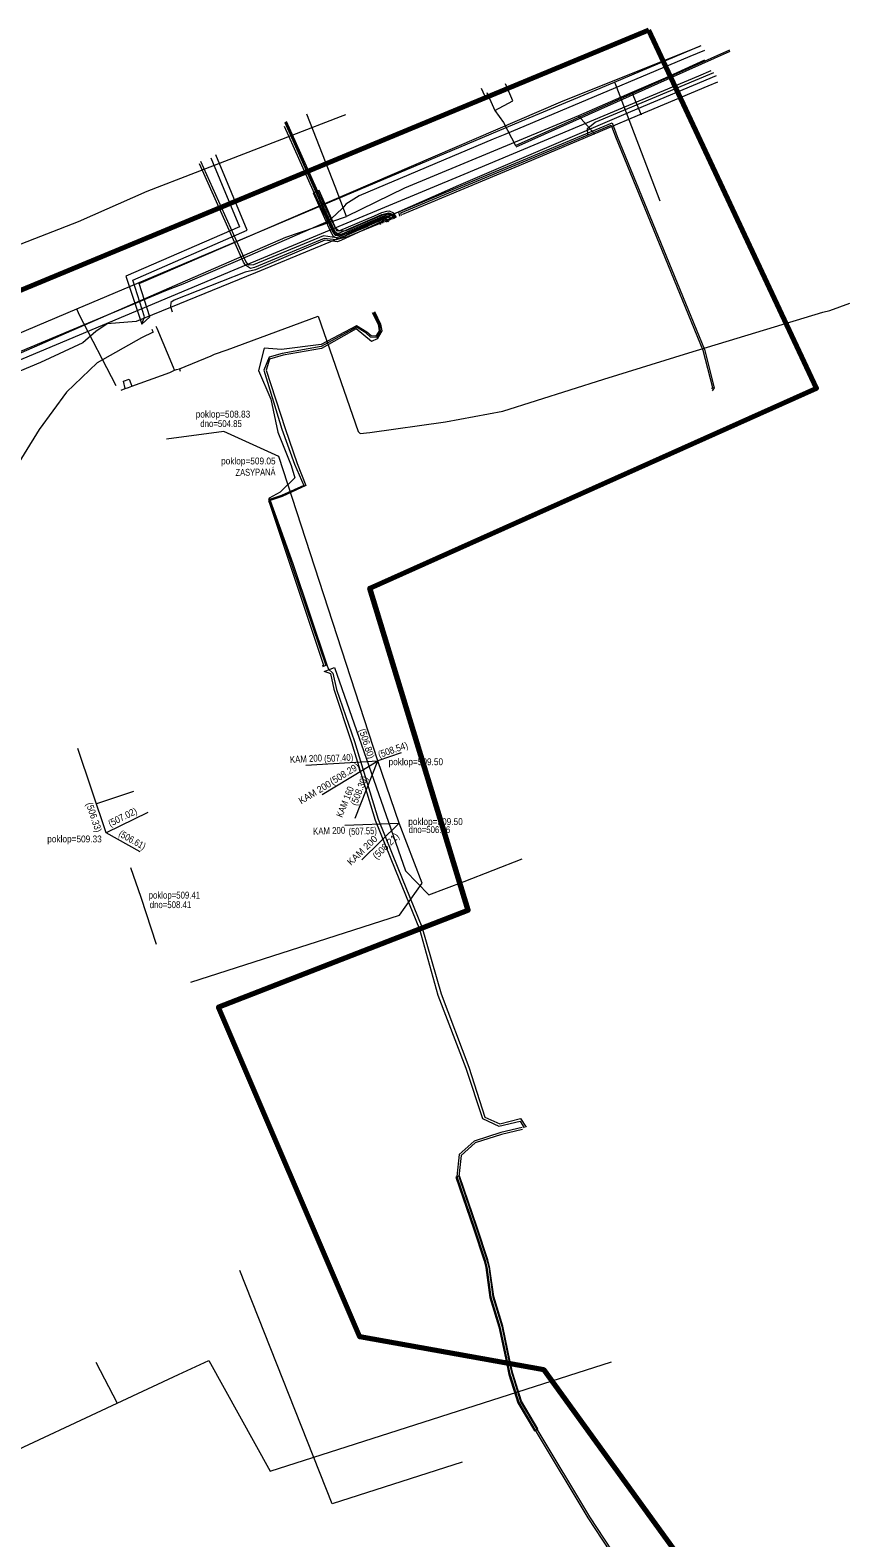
# Model space of a CAD drawing. Extents: x -669700 to -669482, y -1129632 to -1129394.
# Drawn here: x -669565.5 to -669482, y -1129547.5 to -1129393.9 of the extents above; entities that cross this region are included whole.
import ezdxf
from ezdxf.enums import TextEntityAlignment as Align

# ---------------------------------------------------------------- set-up
doc = ezdxf.new("R2010")
doc.units = 0
doc.header["$LTSCALE"] = 0.28
for name, color, linetype, lineweight in [('1', 7, 'Continuous', 13), ('12', 7, 'Continuous', 13), ('13', 7, 'Continuous', 13), ('21', 7, 'Continuous', 13), ('24', 7, 'Continuous', 13), ('27', 7, 'Continuous', 13), ('3', 7, 'Continuous', 13), ('33', 7, 'Continuous', 13), ('43', 7, 'Continuous', 13), ('53', 7, 'Continuous', 13), ('54', 7, 'Continuous', 13), ('57', 7, 'Continuous', 70), ('7', 7, 'Continuous', 13)]:
    doc.layers.add(name, color=color, linetype=linetype, lineweight=lineweight)
doc.layers.add('59', color=7, linetype='Continuous')

msp = doc.modelspace()

# ---------------------------------------------------------------- linework, layer by layer
at = {"layer": '1'}
msp.add_lwpolyline([(-669496.851, -1129395.943), (-669498.33, -1129396.56), (-669511.52, -1129402.13), (-669517.18, -1129404.52), (-669518.35, -1129405), (-669532, -1129410.77), (-669533.35, -1129411.61), (-669533.55, -1129411.87), (-669533.74, -1129412.06), (-669534.83, -1129413.08), (-669535.13, -1129413.35), (-669543.92, -1129417.17), (-669549.97, -1129419.77), (-669551.71, -1129420.43), (-669552.78, -1129420.88), (-669561.46, -1129424.52), (-669573.43, -1129429.51)], dxfattribs=at)
at = {"layer": '12'}
for p, q in [((-669516.08, -1129405.62), (-669494.27, -1129395.9)), ((-669516.36, -1129401.09), (-669517.11, -1129399.37)), ((-669518.2, -1129402.06), (-669516.36, -1129401.09)), ((-669517.31, -1129403.28), (-669516.08, -1129405.62))]:
    msp.add_line(p, q, dxfattribs=at)
for points in [[(-669496.193, -1129398.031), (-669497.44, -1129398.56), (-669521.35, -1129408.58), (-669544.75, -1129418.35), (-669569.27, -1129428.64), (-669593.24, -1129438.67), (-669594.77, -1129439.37), (-669598.74, -1129442.19), (-669598.99, -1129442.41), (-669613.69, -1129455.56), (-669636.45, -1129475.92), (-669654.71, -1129492.21), (-669673.86, -1129509.44), (-669690.21, -1129524.03), (-669693.504, -1129526.678)], [(-669519.01, -1129400.25), (-669518.2, -1129402.06), (-669517.31, -1129403.28)]]:
    msp.add_lwpolyline(points, dxfattribs=at)
at = {"layer": '13'}
for p, q in [((-669516.019, -1129405.757), (-669494.209, -1129396.037)), ((-669558.81, -1129529.58), (-669556.63, -1129533.77)), ((-669580.87, -1129545.11), (-669556.63, -1129533.77))]:
    msp.add_line(p, q, dxfattribs=at)
for points in [[(-669508.71, -1129404.56), (-669508.75, -1129403.9), (-669507.98, -1129403.27), (-669495.868, -1129398.207)], [(-669535.58, -1129459.21), (-669534.5, -1129458.83), (-669527.28, -1129479.55), (-669524.92, -1129481.99), (-669521.32, -1129480.61), (-669515.406, -1129478.323)], [(-669556.63, -1129533.77), (-669550.41, -1129530.86), (-669547.32, -1129529.43), (-669541.05, -1129540.7), (-669506.304, -1129529.571)]]:
    msp.add_lwpolyline(points, dxfattribs=at)
at = {"layer": '21'}
for p, q in [((-669504.25, -1129400.25), (-669503.28, -1129402.52)), ((-669509.66, -1129402.6), (-669508.01, -1129404.49)), ((-669550.3, -1129428.39), (-669550.22, -1129428.62))]:
    msp.add_line(p, q, dxfattribs=at)
for points in [[(-669496.845, -1129396.94), (-669500.84, -1129398.77), (-669504.25, -1129400.25), (-669509.66, -1129402.6), (-669527.39, -1129409.97), (-669533.28, -1129412.87)], [(-669533.28, -1129412.87), (-669534.46, -1129409.81), (-669537.33, -1129402.455)], [(-669550.23, -1129419.66), (-669539.46, -1129414.96), (-669533.28, -1129412.87)], [(-669553.131, -1129424.348), (-669553.08, -1129424.45), (-669552.97, -1129424.66), (-669554.16, -1129425.23), (-669558.7, -1129427.79), (-669561.79, -1129430.76), (-669564.58, -1129434.58), (-669567.92, -1129439.98), (-669576.65, -1129451.91), (-669580.3, -1129456.57), (-669581.62, -1129458.81), (-669581.92, -1129461.49), (-669580.27, -1129467.8), (-669579.78, -1129469.59), (-669577.05, -1129477.92), (-669576.91, -1129478.41), (-669576.3, -1129480.12), (-669576.78, -1129480.36), (-669579.92, -1129481.77), (-669581.02, -1129482.2), (-669583.11, -1129482.87), (-669583.18, -1129482.9)], [(-669550.81, -1129428.51), (-669550.92, -1129428.26), (-669552.59, -1129424.27), (-669552.67, -1129424.09)]]:
    msp.add_lwpolyline(points, dxfattribs=at)
at = {"layer": '24'}
for points in [[(-669664.58, -1129499.83), (-669597.43, -1129440.26), (-669550.23, -1129419.66)], [(-669550.81, -1129428.51), (-669550.59, -1129428.47), (-669550.3, -1129428.39), (-669547.09, -1129427.05), (-669546.74, -1129426.89), (-669545.43, -1129426.45), (-669536.18, -1129423.03), (-669532.09, -1129434.77), (-669531.9, -1129434.99), (-669530.92, -1129434.86), (-669523.2, -1129433.78), (-669517.38, -1129432.71), (-669507.08, -1129429.43), (-669498.43, -1129426.77), (-669484.77, -1129422.63), (-669484.08, -1129422.44), (-669482.034, -1129421.713)], [(-669521.528, -1129539.77), (-669534.742, -1129544.022), (-669544.16, -1129520.24)]]:
    msp.add_lwpolyline(points, dxfattribs=at)
at = {"layer": '27'}
msp.add_line((-669555.82, -1129430.39), (-669555.485, -1129430.28), dxfattribs=at)
for points in [[(-669556.25, -1129430.57), (-669555.82, -1129430.39), (-669556.01, -1129429.65), (-669555.42, -1129429.46), (-669555.27, -1129429.87), (-669555.15, -1129430.17)], [(-669555.485, -1129430.28), (-669555.15, -1129430.17), (-669551.29, -1129428.75), (-669550.81, -1129428.51)]]:
    msp.add_lwpolyline(points, dxfattribs=at)
at = {"layer": '3'}
for points in [[(-669554.15, -1129423.85), (-669553.32, -1129423.1), (-669554.41, -1129419.7), (-669511.48, -1129401.19), (-669497.307, -1129395.524)], [(-669529.586, -1129413.549), (-669529.64, -1129413.271), (-669529.39, -1129413.007), (-669521.845, -1129409.674), (-669504.35, -1129402.165), (-669495.603, -1129398.504)], [(-669527.538, -1129412.689), (-669527.544, -1129412.623), (-669526.927, -1129412.353), (-669515.718, -1129407.674), (-669505.887, -1129403.539), (-669504.292, -1129402.837), (-669496.461, -1129399.542), (-669495.491, -1129399.134)], [(-669529.103, -1129413.449), (-669529.399, -1129413.086), (-669529.63, -1129413.14), (-669533.26, -1129414.64), (-669534.09, -1129414.82), (-669534.44, -1129414.64), (-669534.7, -1129414.21), (-669535.44, -1129412.56), (-669536.41, -1129410.35), (-669539.526, -1129403.331)], [(-669528.988, -1129413.402), (-669529.341, -1129412.973), (-669529.59, -1129413.02), (-669533.28, -1129414.62), (-669534.11, -1129414.69), (-669534.35, -1129414.55), (-669534.65, -1129414.26), (-669535.42, -1129412.4), (-669536.37, -1129410.34), (-669539.515, -1129403.257)], [(-669528.194, -1129412.98), (-669528.473, -1129412.526), (-669528.918, -1129412.334), (-669529.205, -1129412.351), (-669529.743, -1129412.507), (-669530.46, -1129412.826), (-669534.017, -1129414.34), (-669534.209, -1129414.363), (-669534.342, -1129414.191), (-669535.031, -1129412.805), (-669536.334, -1129410.007), (-669539.414, -1129403.181)], [(-669527.866, -1129412.835), (-669527.965, -1129412.394), (-669506.238, -1129403.315), (-669505.725, -1129404.706), (-669496.842, -1129426.424), (-669495.833, -1129430.34), (-669496.051, -1129430.625)], [(-669527.701, -1129412.762), (-669527.76, -1129412.5), (-669506.34, -1129403.55), (-669505.89, -1129404.77), (-669497.01, -1129426.48), (-669496.026, -1129430.301), (-669496.129, -1129430.436)], [(-669547.106, -1129406.904), (-669544.19, -1129413.93), (-669555.75, -1129418.96), (-669554.15, -1129423.85), (-669553.85, -1129423.1), (-669555.06, -1129419.34), (-669543.41, -1129414.27), (-669546.592, -1129406.589)], [(-669528.736, -1129413.221), (-669528.872, -1129413.122), (-669529.048, -1129412.986), (-669529.532, -1129413.138), (-669533.903, -1129415.092), (-669534.33, -1129415.239), (-669535.552, -1129415.099), (-669542.67, -1129418.083), (-669543.072, -1129418.165), (-669543.589, -1129417.844), (-669543.79, -1129417.526), (-669548.265, -1129407.52)], [(-669528.595, -1129413.158), (-669528.778, -1129412.956), (-669529.046, -1129412.824), (-669529.593, -1129412.981), (-669533.986, -1129414.914), (-669534.327, -1129415.027), (-669535.648, -1129414.854), (-669542.764, -1129417.788), (-669543.244, -1129417.832), (-669543.552, -1129417.443), (-669548.12, -1129407.256)], [(-669529.803, -1129413.675), (-669530.029, -1129413.31), (-669530.213, -1129413.348), (-669530.864, -1129413.674), (-669531.217, -1129413.925), (-669536.492, -1129416.091), (-669542.545, -1129418.613), (-669554.722, -1129423.573), (-669557.657, -1129423.8), (-669558.831, -1129424.585), (-669560.14, -1129425.741), (-669564.467, -1129427.729), (-669594.248, -1129440.232), (-669598.12, -1129442.702), (-669644.235, -1129483.951), (-669685.258, -1129519.89), (-669686.935, -1129521.259), (-669687.43, -1129521.755), (-669687.51, -1129522.187), (-669687.241, -1129522.483), (-669687.013, -1129522.747)], [(-669528.893, -1129413.29), (-669529.087, -1129413.18), (-669529.447, -1129413.292), (-669533.815, -1129415.277), (-669534.214, -1129415.446), (-669535.483, -1129415.288), (-669542.561, -1129418.292), (-669543.613, -1129418.539), (-669550.839, -1129421.402), (-669551.19, -1129421.638), (-669551.205, -1129422.037), (-669551.04, -1129422.594)], [(-669530.672, -1129422.667), (-669530.073, -1129423.853), (-669529.963, -1129424.515), (-669530.291, -1129425.073), (-669530.772, -1129425.022), (-669531.222, -1129424.663), (-669532.262, -1129424.008), (-669535.88, -1129425.92), (-669539.9, -1129426.42), (-669541.66, -1129426.27), (-669542.26, -1129428.55), (-669541.01, -1129431.48), (-669540.29, -1129434.83), (-669538.94, -1129438.25), (-669538.55, -1129439.51), (-669540.06, -1129440.97), (-669541.16, -1129441.56), (-669541.22, -1129441.79), (-669541.072, -1129442.279), (-669535.621, -1129458.579), (-669535.756, -1129458.635)], [(-669530.554, -1129422.617), (-669529.94, -1129423.9), (-669529.85, -1129424.56), (-669530.24, -1129425.2), (-669530.85, -1129425.18), (-669531.33, -1129424.72), (-669532.28, -1129424.16), (-669535.88, -1129426.13), (-669539.83, -1129426.82), (-669541.16, -1129427.21), (-669541.7, -1129428.52), (-669539.88, -1129434.55), (-669538.6, -1129438.12), (-669537.65, -1129440.26), (-669539.91, -1129441.31), (-669541.15, -1129441.7), (-669541.1, -1129441.93), (-669539.464, -1129446.579), (-669535.385, -1129458.605), (-669535.737, -1129458.74)], [(-669530.427, -1129422.566), (-669529.816, -1129423.834), (-669529.69, -1129424.52), (-669530.156, -1129425.35), (-669530.75, -1129425.59), (-669532.313, -1129424.316), (-669535.84, -1129426.32), (-669539.75, -1129427.01), (-669541.12, -1129427.39), (-669541.47, -1129428.54), (-669539.55, -1129434.46), (-669538.31, -1129438.05), (-669537.45, -1129440.28), (-669539.84, -1129441.41), (-669541.06, -1129441.81), (-669538.759, -1129448.231), (-669535.262, -1129458.643), (-669535.129, -1129458.977), (-669534.67, -1129459.39), (-669534.302, -1129461.048), (-669532.49, -1129466.37), (-669530.068, -1129474.262), (-669528.054, -1129479.219), (-669525.61, -1129485.247), (-669523.662, -1129492.082), (-669520.826, -1129499.546), (-669519.192, -1129504.633), (-669517.67, -1129505.3), (-669515.556, -1129504.764), (-669514.98, -1129505.652)], [(-669535.568, -1129459.195), (-669534.91, -1129459.44), (-669534.57, -1129461.03), (-669532.78, -1129466.45), (-669530.356, -1129474.367), (-669528.342, -1129479.389), (-669525.86, -1129485.47), (-669523.989, -1129492.2), (-669521.14, -1129499.624), (-669519.454, -1129504.764), (-669517.766, -1129505.549), (-669515.609, -1129505.025), (-669515.211, -1129505.728)], [(-669515.403, -1129505.693), (-669517.577, -1129506.204), (-669520.281, -1129507.071), (-669521.815, -1129508.431), (-669522.062, -1129510.691), (-669520.265, -1129515.952), (-669519.176, -1129519.238), (-669519.008, -1129519.919), (-669518.588, -1129522.971), (-669517.677, -1129525.985), (-669516.908, -1129529.621), (-669516.656, -1129530.818), (-669516.555, -1129531.083), (-669515.742, -1129533.701), (-669514.066, -1129536.531), (-669508.715, -1129545.463), (-669505.724, -1129550.014)], [(-669515.357, -1129505.887), (-669517.523, -1129506.396), (-669520.179, -1129507.249), (-669521.625, -1129508.529), (-669521.858, -1129510.669), (-669520.075, -1129515.888), (-669518.984, -1129519.182), (-669518.812, -1129519.881), (-669518.392, -1129522.929), (-669517.483, -1129525.935), (-669516.712, -1129529.579), (-669516.464, -1129530.762), (-669516.365, -1129531.017), (-669515.558, -1129533.619), (-669513.894, -1129536.429), (-669508.545, -1129545.357), (-669505.556, -1129549.906)]]:
    msp.add_lwpolyline(points, dxfattribs=at)
at = {"layer": '33'}
for points in [[(-669536.68, -1129410.47), (-669534.96, -1129414.34), (-669534.66, -1129414.87), (-669534.12, -1129415.13), (-669533.17, -1129414.92), (-669529.53, -1129413.42), (-669529.19, -1129413.34), (-669528.52, -1129412.88), (-669529.06, -1129412.61), (-669529.67, -1129412.73), (-669533.35, -1129414.32), (-669534.04, -1129414.38), (-669534.39, -1129414.09), (-669535.15, -1129412.28), (-669536.09, -1129410.21)], [(-669521.771, -1129510.615), (-669522.149, -1129510.745), (-669520.36, -1129515.984), (-669519.272, -1129519.265), (-669519.107, -1129519.938), (-669518.686, -1129522.993), (-669517.774, -1129526.01), (-669517.006, -1129529.641), (-669516.754, -1129530.841), (-669515.834, -1129533.742), (-669514.152, -1129536.582), (-669513.808, -1129536.378), (-669515.466, -1129533.578), (-669516.366, -1129530.739), (-669516.614, -1129529.559), (-669517.386, -1129525.91), (-669518.294, -1129522.907), (-669518.713, -1129519.862), (-669518.888, -1129519.155), (-669519.98, -1129515.856)]]:
    msp.add_lwpolyline(points, close=True, dxfattribs=at)
at = {"layer": '43'}
for points in [[(-669694.908, -1129524.298), (-669603.762, -1129441.878), (-669570.159, -1129426.24), (-669560.762, -1129422.274), (-669515.5, -1129403.171), (-669505.996, -1129399.186), (-669497.189, -1129395.46)], [(-669505.996, -1129399.186), (-669505.907, -1129399.42), (-669501.367, -1129411.272)], [(-669699.691, -1129518.563), (-669690.798, -1129510.637), (-669678.579, -1129499.988), (-669678.26, -1129499.71), (-669655.611, -1129479.364), (-669624.757, -1129451.648), (-669602.694, -1129432.07), (-669599.579, -1129430.433), (-669599.26, -1129430.29), (-669586.084, -1129424.373), (-669574.529, -1129419.183), (-669573.296, -1129418.679), (-669567.039, -1129415.878), (-669560.587, -1129413.39), (-669553.6, -1129410.28), (-669533.914, -1129402.69), (-669533.37, -1129402.48)], [(-669556.75, -1129430.12), (-669560.52, -1129422.86), (-669560.762, -1129422.274)]]:
    msp.add_lwpolyline(points, dxfattribs=at)
at = {"layer": '53'}
msp.add_line((-669519.577, -1129399.79), (-669519.082, -1129400.919), dxfattribs=at)
at = {"layer": '54'}
for p, q in [((-669545.78, -1129434.77), (-669551.609, -1129435.555)), ((-669557.76, -1129475.67), (-669560.657, -1129467.079)), ((-669527.715, -1129467.506), (-669530.1, -1129468.34)), ((-669537.421, -1129468.754), (-669530.1, -1129468.34)), ((-669535.757, -1129471.76), (-669530.1, -1129468.34)), ((-669532.413, -1129474.169), (-669530.1, -1129468.34)), ((-669554.99, -1129471.44), (-669558.755, -1129472.721)), ((-669553.511, -1129473.579), (-669557.76, -1129475.67)), ((-669554.292, -1129477.614), (-669557.76, -1129475.67)), ((-669533.45, -1129474.866), (-669527.92, -1129474.68)), ((-669531.742, -1129478.408), (-669527.92, -1129474.68))]:
    msp.add_line(p, q, dxfattribs=at)
for points in [[(-669549.15, -1129490.88), (-669527.903, -1129484.035), (-669525.584, -1129480.788), (-669527.92, -1129474.68), (-669530.1, -1129468.34), (-669540.17, -1129437.32), (-669545.78, -1129434.77)], [(-669552.633, -1129487.033), (-669554.2, -1129482.25), (-669555.267, -1129479.22)]]:
    msp.add_lwpolyline(points, dxfattribs=at)
at = {"layer": '57'}
msp.add_lwpolyline([(-669502.497, -1129393.885), (-669582.414, -1129427.001), (-669584.503, -1129421.96), (-669596.844, -1129427.074), (-669598.13, -1129433.022), (-669691.757, -1129513.637), (-669682.395, -1129529.024), (-669666.679, -1129550.432), (-669641.934, -1129592.579), (-669614.849, -1129632.05), (-669490.459, -1129561.805), (-669513.197, -1129530.362), (-669531.922, -1129527.017), (-669546.343, -1129493.441), (-669520.888, -1129483.532), (-669530.919, -1129450.75), (-669485.443, -1129430.346)], close=True, dxfattribs=at)
at = {"layer": '7'}
for points in [[(-669539.511, -1129403.391), (-669536.468, -1129410.078), (-669534.464, -1129414.391), (-669534.326, -1129414.58), (-669534.071, -1129414.568), (-669530.368, -1129412.964), (-669529.687, -1129412.651), (-669529.028, -1129412.486), (-669528.594, -1129412.624), (-669528.335, -1129413.043)], [(-669539.655, -1129403.663), (-669536.725, -1129410.176), (-669534.682, -1129414.483), (-669534.463, -1129414.757), (-669534.21, -1129414.822), (-669534.027, -1129414.78), (-669529.604, -1129412.824), (-669529.067, -1129412.662), (-669528.714, -1129412.766), (-669528.451, -1129413.094)]]:
    msp.add_lwpolyline(points, dxfattribs=at)

# ---------------------------------------------------------------- texts
at = {"layer": '59'}
for s, width, p in [('poklop=508.83 ', 0.9, (-669545.7545, -1129433.358)), ('dno=504.85', 0.85, (-669546.0645, -1129434.321)), ('poklop=509.05 ', 0.9, (-669543.172, -1129438.128)), ('poklop=509.50 ', 0.9, (-669526.115, -1129468.771)), ('poklop=509.50 ', 0.9, (-669524.11, -1129474.871)), ('dno=506.96', 0.85, (-669524.847, -1129475.687)), ('poklop=509.33 ', 0.9, (-669560.8745, -1129476.636)), ('poklop=509.41 ', 0.85, (-669550.708, -1129482.364)), ('dno=508.41', 0.85, (-669551.2185, -1129483.334))]:
    msp.add_text(s, height=0.7, dxfattribs=dict(at, width=width)).set_placement(p, align=Align.CENTER)
for s, rotation, width, p in [('ZASYPANÁ', 0.718, 0.75, (-669542.5524, -1129439.2698)), ('(506.80)', 287.982, 0.9, (-669531.5615, -1129466.6899)), ('(508.54)', 19.268, 0.9, (-669528.453, -1129467.5349)), ('KAM 200', 3.237, 0.85, (-669537.3993, -1129468.4663)), ('(507.40)', 3.236, 0.85, (-669534.0718, -1129468.3841)), ('(508.29)', 31.154, 0.95, (-669533.3101, -1129469.9393)), ('KAM 200', 31.158, 0.95, (-669536.3371, -1129471.8253)), ('KAM 160', 68.358, 0.85, (-669533.1163, -1129472.6381)), ('(508.30)', 68.358, 0.9, (-669531.6834, -1129471.4921)), ('(506.33)', 288.63, 0.9, (-669559.3402, -1129474.1877)), ('(507.02)', 26.199, 0.9, (-669555.941, -1129474.3696)), ('(506.61)', 330.743, 0.85, (-669555.2761, -1129476.6922)), ('KAM 200', 1.929, 0.85, (-669535.0508, -1129475.7944)), ('(507.55)', 1.929, 0.8, (-669531.6293, -1129475.8296)), ('(508.21)', 44.291, 0.95, (-669529.0394, -1129477.2549))]:
    msp.add_text(s, height=0.7, rotation=rotation, dxfattribs=dict(at, width=width)).set_placement(p, align=Align.CENTER)
msp.add_text('KAM 200', height=0.7, rotation=44.285, dxfattribs=at).set_placement((-669531.4439, -1129477.7068), align=Align.CENTER)

doc.saveas('drawing.dxf')
